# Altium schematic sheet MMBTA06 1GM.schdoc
size 127 x 101 mm
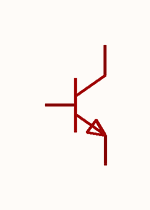
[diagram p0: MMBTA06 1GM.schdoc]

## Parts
Q?  mmbta06(range:100-400)  [SOT-23-3_L2.9-W1.6-P1.90-LS2.8-BR]  (value not drawn)

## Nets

Not connected (* = marked no-connect by the designer): Q? 1(B) 2(E) 3(C)

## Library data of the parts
Q? = mmbta06(range:100-400): 晶体管类型:NPN;集电极电流(Ic):500mA;集射极击穿电压(Vceo):80V;耗散功率(Pd):300mW;直流电流增益(hFE):100;; Manufacturer: CJ(江苏长电/长晶); Symbol: MMBTA06 1GM; AddInBom: yes; ModelId: 89cb27a44ab2466697082bb9fd73a7d0; ModelName: SOT-23-3L_L2.9-W1.6-H1.1-LS2.8-P0.95; ModelTransform: 114.173,110.236,0,90,0,0,0,0,0; type: NPN; Current - Collector(Ic): 500mA; Collector - Emitter Voltage VCEO: 80V; Pd - Power Dissipation: 300mW; DC Current Gain: 100; Transition frequency(fT): 100MHz; Current - Collector Cutoff: 100nA; Vce Saturation(VCE(sat)): 250mV; Emitter-Base Voltage(Vebo): 4V; Number: 1个NPN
